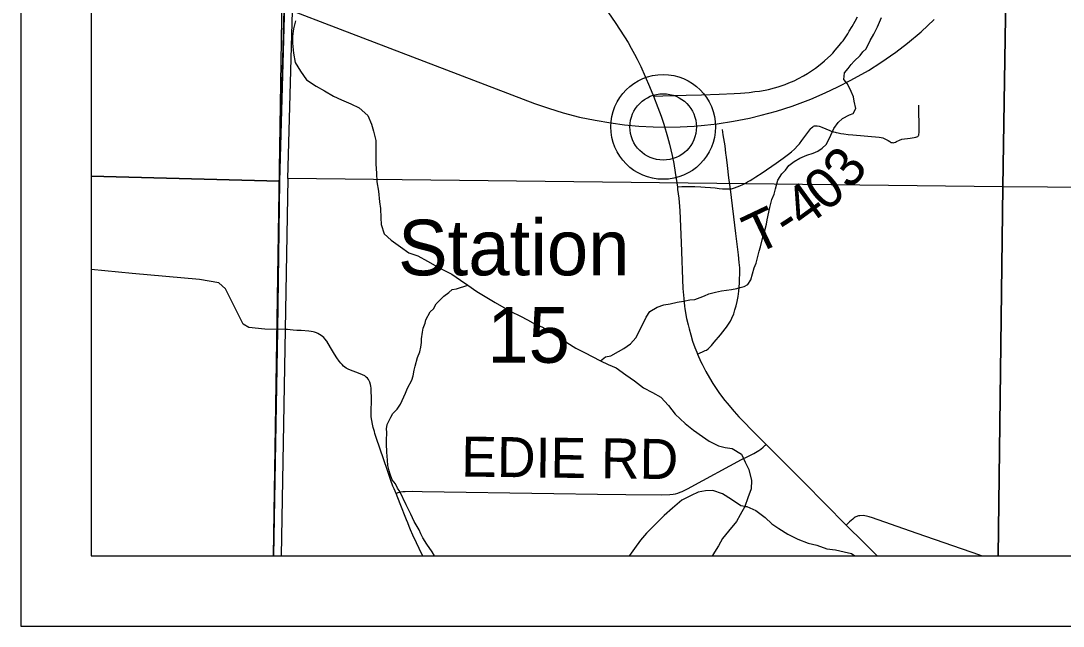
# Model space of a CAD drawing. Extents: x -1.2 to 34, y -8.5 to 22.
# Drawn here: x 2 to 3.48, y 14 to 14.86 of the extents above; entities that cross this region are included whole.
import ezdxf

# ---------------------------------------------------------------- set-up
doc = ezdxf.new("R2010")
doc.units = 0
for name, color, linetype in [('DV_X_County_Line', 7, 'Continuous'), ('GM_X_County_Road', 7, 'Continuous'), ('GM_X_Major_River', 7, 'Continuous'), ('GM_X_Minor_River', 7, 'Continuous'), ('GM_X_Rail_Line', 7, 'Continuous'), ('GM_X_Section', 7, 'Continuous'), ('GM_X_State_Route', 7, 'Continuous'), ('GM_X_Township_Road', 7, 'Continuous'), ('GM_X_Township_Road_Text', 7, 'Continuous'), ('GM_X_Unincorporated', 7, 'Continuous'), ('GM_X_Unincorporated_Location', 7, 'Continuous'), ('GM_X_Unincorporated_Text', 7, 'Continuous'), ('GM_X_US_Route', 7, 'Continuous'), ('SH_Cut_Line', 7, 'Continuous'), ('SH_Data', 7, 'Continuous')]:
    doc.layers.add(name, color=color, linetype=linetype)

msp = doc.modelspace()

# ---------------------------------------------------------------- linework, layer by layer
at = {"layer": 'DV_X_County_Line'}
msp.add_line((2.3586, 14.1), (2.465, 20.9), dxfattribs=at)
at = {"layer": 'GM_X_County_Road'}
for points in [[(3.0079, 14.6207), (3.0057, 14.637), (3.0035, 14.6544), (3.0021, 14.6661), (3.0014, 14.672), (3.0008, 14.6772), (3.0001, 14.6823), (2.9976, 14.6977), (2.9963, 14.7055)], [(3.0079, 14.6207), (3.0045, 14.6205), (2.9967, 14.6207), (2.9916, 14.6213), (2.986, 14.6219), (2.9793, 14.6227), (2.972, 14.6232), (2.9657, 14.6234), (2.9571, 14.6238), (2.9487, 14.6239), (2.9387, 14.6238), (2.9324, 14.6235)], [(2.9849, 14.4035), (2.9936, 14.4136), (3.0004, 14.4221), (3.0023, 14.4246), (3.0051, 14.4288), (3.0077, 14.4333), (3.0098, 14.4374), (3.0124, 14.4437), (3.0142, 14.4493), (3.0158, 14.4549), (3.0172, 14.4611), (3.0186, 14.4682), (3.0198, 14.4758), (3.0202, 14.4811), (3.0206, 14.4881), (3.021, 14.5052), (3.0209, 14.509), (3.0204, 14.5166), (3.0193, 14.5272), (3.0156, 14.5576), (3.0079, 14.6207)], [(2.9612, 14.3863), (2.972, 14.3913), (2.9736, 14.3922), (2.9761, 14.3938), (2.9777, 14.3952), (2.9809, 14.3988), (2.9849, 14.4035)], [(3.2061, 14.1548), (3.205, 14.1552), (3.203, 14.1559), (3.2012, 14.1563), (3.1988, 14.1568), (3.1961, 14.157), (3.1914, 14.1569), (3.1897, 14.1566), (3.1884, 14.1562), (3.1871, 14.1558), (3.1858, 14.1552), (3.1847, 14.1546), (3.1836, 14.1537), (3.1814, 14.1517), (3.1792, 14.1499), (3.1771, 14.1481), (3.1723, 14.1435)], [(3.3641, 14.1), (3.3619, 14.1008), (3.2731, 14.1315), (3.2633, 14.1348), (3.2082, 14.1541), (3.2061, 14.1548)]]:
    msp.add_lwpolyline(points, dxfattribs=at)
at = {"layer": 'GM_X_Major_River'}
msp.add_lwpolyline([(2.39, 14.8598), (2.3871, 14.8484), (2.3857, 14.8382), (2.3858, 14.8279), (2.3874, 14.8139), (2.3898, 14.8007), (2.3971, 14.7882), (2.4055, 14.7761), (2.4192, 14.7671), (2.4313, 14.7604), (2.4439, 14.7526), (2.4556, 14.7477), (2.4685, 14.7418), (2.4807, 14.7362), (2.4929, 14.7253), (2.4979, 14.7128), (2.501, 14.7029), (2.5042, 14.6897), (2.5043, 14.6662), (2.504, 14.6563), (2.5049, 14.6434), (2.5058, 14.6309), (2.5078, 14.6177), (2.5094, 14.6029), (2.511, 14.593), (2.5111, 14.5798), (2.5119, 14.5703), (2.5158, 14.5574), (2.5261, 14.5484), (2.5391, 14.5387), (2.5512, 14.5304), (2.5637, 14.526), (2.5774, 14.5185), (2.5919, 14.5103), (2.6017, 14.505), (2.612, 14.4998), (2.6245, 14.4916), (2.6348, 14.4844), (2.6477, 14.4754), (2.6736, 14.4597), (2.6861, 14.4526), (2.696, 14.447), (2.7097, 14.4403), (2.7196, 14.435), (2.7306, 14.4287), (2.7408, 14.4246), (2.753, 14.4175), (2.7659, 14.4092), (2.7754, 14.4029), (2.788, 14.3946), (2.8013, 14.3883), (2.8115, 14.3831), (2.8233, 14.3767), (2.8343, 14.3715), (2.8457, 14.3667), (2.8594, 14.3569), (2.8716, 14.3483), (2.8845, 14.3385), (2.897, 14.3318), (2.9088, 14.3254), (2.9199, 14.3134), (2.9294, 14.301), (2.9435, 14.2878), (2.9553, 14.2784), (2.9683, 14.2694), (2.9778, 14.2627), (2.9907, 14.2563), (3.0002, 14.2537), (3.01, 14.2523), (3.0237, 14.2444), (3.0287, 14.2327), (3.0337, 14.2225), (3.0376, 14.207), (3.037, 14.1949), (3.0325, 14.1823), (3.0281, 14.1701), (3.0218, 14.1583), (3.0165, 14.1484), (3.0049, 14.1351), (2.9967, 14.1244), (2.9907, 14.1141), (2.9829, 14.1011), (2.9822, 14.1)], dxfattribs=at)
at = {"layer": 'GM_X_Minor_River'}
for points in [[(2.8233, 14.3767), (2.8304, 14.3824), (2.838, 14.384), (2.8488, 14.3899), (2.8564, 14.3942), (2.8657, 14.4008), (2.8732, 14.4097), (2.8827, 14.4281), (2.8879, 14.4388), (2.8931, 14.4469), (2.9036, 14.4531), (2.9134, 14.4563), (2.9224, 14.458), (2.9319, 14.46), (2.9413, 14.4617), (2.95, 14.4634), (2.9572, 14.4642), (2.9647, 14.4666), (2.9711, 14.4694), (2.9771, 14.4718), (2.9866, 14.4746), (2.9952, 14.4762), (3.002, 14.4771), (3.0092, 14.478), (3.0168, 14.4796), (3.0217, 14.4808), (3.0273, 14.4824), (3.0326, 14.4852), (3.0367, 14.4921), (3.0417, 14.5089), (3.0443, 14.5158), (3.0486, 14.5326), (3.0507, 14.5387), (3.0547, 14.5563), (3.0565, 14.5621), (3.059, 14.5712), (3.06, 14.577), (3.0636, 14.5945), (3.0668, 14.606), (3.0697, 14.6136), (3.0719, 14.6213), (3.0751, 14.6335), (3.081, 14.6424), (3.0859, 14.6478), (3.0907, 14.6543), (3.0982, 14.6598), (3.1065, 14.6648), (3.1162, 14.6692), (3.1253, 14.672), (3.1321, 14.6747), (3.1381, 14.679), (3.1437, 14.6841), (3.1485, 14.6929), (3.1547, 14.7071), (3.1606, 14.7155), (3.167, 14.7209), (3.1771, 14.7264), (3.182, 14.7284), (3.1857, 14.7353), (3.1836, 14.7456), (3.1824, 14.752), (3.1793, 14.7592), (3.1738, 14.7702), (3.1688, 14.7765), (3.1698, 14.7861), (3.175, 14.7922), (3.1791, 14.7976), (3.1836, 14.8027), (3.1918, 14.8104), (3.1959, 14.8158), (3.2007, 14.82), (3.2062, 14.8319), (3.2114, 14.8408), (3.2166, 14.8511), (3.2224, 14.8645)], [(2.6005, 14.4686), (2.6076, 14.4741), (2.6128, 14.4783), (2.6185, 14.4792), (2.6348, 14.4844)], [(2.5876, 14.1), (2.5842, 14.1057), (2.5764, 14.1166), (2.571, 14.1253), (2.5683, 14.1313), (2.5656, 14.1366), (2.5586, 14.1487), (2.5539, 14.1589), (2.5472, 14.1725), (2.5383, 14.191), (2.5348, 14.1959), (2.532, 14.2019), (2.5274, 14.2076), (2.5246, 14.2159), (2.5231, 14.2208), (2.5214, 14.2284), (2.5206, 14.2356), (2.5196, 14.247), (2.5191, 14.2588), (2.5194, 14.2638), (2.5196, 14.2752), (2.5195, 14.2801), (2.5202, 14.2866), (2.5253, 14.297), (2.5283, 14.302), (2.5346, 14.3082), (2.5391, 14.3151), (2.5439, 14.3258), (2.5464, 14.3308), (2.549, 14.3381), (2.5552, 14.3492), (2.557, 14.3557), (2.5588, 14.3637), (2.5599, 14.3691), (2.5631, 14.3817), (2.5668, 14.3897), (2.5682, 14.3962), (2.5689, 14.4027), (2.5692, 14.408), (2.5702, 14.4176), (2.5712, 14.4233), (2.5741, 14.4302), (2.5752, 14.4351), (2.5811, 14.4466), (2.5859, 14.4509), (2.59, 14.4578), (2.6005, 14.4686)], [(3.0281, 14.1701), (3.0224, 14.1709), (3.0091, 14.1799), (2.9966, 14.1881), (2.9829, 14.1925), (2.9723, 14.1921), (2.9621, 14.1905), (2.9519, 14.1855), (2.9388, 14.1789), (2.9256, 14.1674), (2.9136, 14.1571), (2.9012, 14.1449), (2.8885, 14.1322), (2.8802, 14.1219), (2.8713, 14.1105), (2.8642, 14.1002), (2.8641, 14.1)], [(3.0281, 14.1701), (3.0311, 14.1698), (3.044, 14.1642), (3.057, 14.1541), (3.0665, 14.1454), (3.0764, 14.1387), (3.0893, 14.1304), (3.1034, 14.1237), (3.1182, 14.1178), (3.1303, 14.1148), (3.1447, 14.11), (3.1568, 14.1082), (3.1693, 14.1057), (3.1795, 14.1031), (3.1846, 14.1)]]:
    msp.add_lwpolyline(points, dxfattribs=at)
at = {"layer": 'GM_X_Rail_Line'}
msp.add_lwpolyline([(2.3745, 14.8781), (2.4533, 14.8478), (2.5882, 14.7964), (2.7294, 14.7425), (2.7492, 14.7358), (2.7701, 14.7293), (2.7936, 14.7231), (2.8157, 14.7186), (2.8381, 14.7148), (2.8573, 14.7121), (2.8778, 14.7104), (2.898, 14.7092), (2.9154, 14.7089), (2.9365, 14.7092), (2.9561, 14.7104), (2.9709, 14.7117), (2.9888, 14.7135), (3.012, 14.7172), (3.0347, 14.7217), (3.0515, 14.7256), (3.0731, 14.7317), (3.0954, 14.7387), (3.122, 14.7487), (3.1421, 14.7576), (3.1604, 14.766), (3.1787, 14.7755), (3.204, 14.7894), (3.2215, 14.8006), (3.2429, 14.8151), (3.2591, 14.8282), (3.2787, 14.8443), (3.2972, 14.8616)], dxfattribs=at)
at = {"layer": 'GM_X_Section'}
for points in [[(3.4107, 15.6483), (3.3946, 14.624), (2.3794, 14.636), (2.4074, 15.6568)], [(3.4107, 15.6483), (4.4223, 15.6306), (4.409, 14.6166), (3.3946, 14.624)], [(2.3696, 14.1), (3.388, 14.1), (3.3946, 14.624), (2.3794, 14.636)], [(3.388, 14.1), (4.3964, 14.1), (4.409, 14.6166), (3.3946, 14.624)]]:
    msp.add_lwpolyline(points, close=True, dxfattribs=at)
at = {"layer": 'GM_X_State_Route'}
msp.add_lwpolyline([(2.8986, 14.7529), (2.9116, 14.7533), (2.9451, 14.7543), (2.9668, 14.7549), (2.992, 14.7556), (3.013, 14.7565), (3.0221, 14.7571), (3.0342, 14.7581), (3.0426, 14.7592), (3.0492, 14.7601), (3.0572, 14.7615), (3.0616, 14.7624), (3.0704, 14.7646), (3.0757, 14.7662), (3.0853, 14.7694), (3.0908, 14.7715), (3.0982, 14.7748), (3.1042, 14.7779), (3.1114, 14.7819), (3.1174, 14.7852), (3.1245, 14.7898), (3.1284, 14.7926), (3.1374, 14.7997), (3.1415, 14.8031), (3.1503, 14.8112), (3.1531, 14.8141), (3.1565, 14.8179), (3.1622, 14.8247), (3.1661, 14.8294), (3.1677, 14.8316), (3.1744, 14.8415), (3.1766, 14.845), (3.1805, 14.8516), (3.1848, 14.8593), (3.188, 14.8653)], dxfattribs=at)
at = {"layer": 'GM_X_Township_Road'}
for points in [[(3.151, 14.7032), (3.154, 14.7023), (3.1563, 14.7017), (3.1579, 14.7012), (3.1609, 14.7006), (3.1644, 14.6999), (3.169, 14.6992), (3.1748, 14.6983), (3.1814, 14.6977), (3.2192, 14.6946), (3.2218, 14.6942), (3.2242, 14.6936), (3.2271, 14.6924), (3.2297, 14.691), (3.2319, 14.6896), (3.2341, 14.6882), (3.2358, 14.6872), (3.2373, 14.6868), (3.239, 14.6867), (3.2404, 14.6869), (3.242, 14.6876), (3.2437, 14.6884), (3.248, 14.6903), (3.2514, 14.6915), (3.2549, 14.6922), (3.2592, 14.6928), (3.2632, 14.6932), (3.2689, 14.694), (3.271, 14.6945), (3.2726, 14.6949), (3.2737, 14.6956), (3.2743, 14.6962), (3.2749, 14.697), (3.2751, 14.6976), (3.2755, 14.6989), (3.2757, 14.7006), (3.2759, 14.7036), (3.2752, 14.7401)], [(3.0079, 14.6207), (3.0135, 14.6227), (3.0174, 14.624), (3.0212, 14.6255), (3.0253, 14.6274), (3.0294, 14.6292), (3.0322, 14.6309), (3.0357, 14.633), (3.0396, 14.6354), (3.0437, 14.638), (3.0529, 14.6441), (3.0728, 14.6578), (3.0825, 14.6646), (3.0902, 14.6702), (3.0947, 14.6739), (3.0989, 14.6777), (3.1037, 14.6825), (3.1058, 14.6849), (3.1093, 14.6896), (3.1221, 14.7069), (3.1231, 14.708), (3.1246, 14.7093), (3.1257, 14.71), (3.1273, 14.7105), (3.1288, 14.7107), (3.1309, 14.7106), (3.1336, 14.7102), (3.1352, 14.7097), (3.1378, 14.7088), (3.149, 14.7038), (3.151, 14.7032)], [(2.3764, 14.4215), (2.3463, 14.4217), (2.3236, 14.4242), (2.3159, 14.4287), (2.3024, 14.4555), (2.2905, 14.479), (2.2813, 14.4876), (2.2536, 14.4924), (2.1583, 14.5011), (2.1, 14.5064)], [(2.5328, 14.1885), (2.5316, 14.1916), (2.5301, 14.195), (2.5285, 14.199), (2.5256, 14.2068), (2.5226, 14.2153), (2.5207, 14.221), (2.5047, 14.2681), (2.5039, 14.2707), (2.5029, 14.2736), (2.5021, 14.2763), (2.5012, 14.2791), (2.5003, 14.2821), (2.4992, 14.2869), (2.4983, 14.2922), (2.4977, 14.2975), (2.4974, 14.3019), (2.4978, 14.3236), (2.4977, 14.3347), (2.4974, 14.3378), (2.497, 14.3407), (2.4965, 14.3433), (2.4956, 14.3464), (2.4948, 14.3484), (2.4938, 14.3502), (2.4923, 14.352), (2.4906, 14.3536), (2.4884, 14.3553), (2.4852, 14.357), (2.4817, 14.3585), (2.4657, 14.3646), (2.4639, 14.3655), (2.462, 14.3666), (2.4603, 14.3678), (2.4582, 14.3694), (2.4563, 14.3714), (2.4543, 14.3736), (2.4519, 14.3766), (2.4488, 14.3812), (2.4455, 14.3864), (2.44, 14.3956), (2.4344, 14.4046), (2.4317, 14.4079), (2.4301, 14.4098), (2.4284, 14.4115), (2.4264, 14.413), (2.4243, 14.4144), (2.4219, 14.4156), (2.4198, 14.4166), (2.417, 14.4175), (2.4151, 14.418), (2.4123, 14.4185), (2.4088, 14.4188), (2.3981, 14.4197), (2.392, 14.4201), (2.3866, 14.4205), (2.3826, 14.4209), (2.3787, 14.4213), (2.3764, 14.4215)], [(2.8592, 14.1872), (2.9102, 14.1867), (2.9218, 14.1869), (2.9262, 14.1875), (2.9297, 14.1881), (2.9329, 14.189), (2.9364, 14.1902), (2.939, 14.1913), (2.9479, 14.1956), (2.952, 14.1978), (3.0236, 14.2365), (3.0324, 14.2411), (3.0408, 14.2454), (3.0457, 14.2479), (3.0482, 14.2494), (3.0508, 14.2514), (3.0541, 14.2543), (3.0573, 14.2571), (3.0585, 14.2582)], [(2.5328, 14.1885), (2.536, 14.1897), (2.5395, 14.1906), (2.5426, 14.1912), (2.5459, 14.1914), (2.5562, 14.1915), (2.5701, 14.1914), (2.7569, 14.1883), (2.8192, 14.1876), (2.8592, 14.1872)], [(2.5707, 14.1), (2.5687, 14.1043), (2.5658, 14.1103), (2.5618, 14.1184), (2.5567, 14.1291), (2.5532, 14.1368), (2.5514, 14.1414), (2.5494, 14.1465), (2.5477, 14.1509), (2.5386, 14.1737), (2.5328, 14.1885)]]:
    msp.add_lwpolyline(points, dxfattribs=at)
at = {"layer": 'GM_X_Unincorporated'}
for radius in [0.0744, 0.0472]:
    msp.add_circle((2.9123, 14.7091), radius, dxfattribs=at)
at = {"layer": 'GM_X_Unincorporated_Location'}
msp.add_line((2.9123, 14.7091), (2.9123, 14.7091), dxfattribs=at)
at = {"layer": 'GM_X_Unincorporated_Text'}
for p, q in [((2.1, 20.6871), (2.1, 14.6393)), ((2.3867, 15.3183), (2.3672, 14.6322)), ((2.3672, 14.6322), (2.3867, 15.3183)), ((2.1, 14.6393), (2.3672, 14.6322)), ((2.3672, 14.6322), (2.3643, 14.4203)), ((2.3643, 14.4203), (2.3586, 14.1)), ((2.3586, 14.1), (8.2551, 14.1))]:
    msp.add_line(p, q, dxfattribs=at)
msp.add_lwpolyline([(2.1, 14.6393), (2.1, 14.1), (2.3586, 14.1), (2.3643, 14.4203), (2.3672, 14.6322)], close=True, dxfattribs=at)
at = {"layer": 'GM_X_US_Route'}
for points in [[(2.7188, 15.0404), (2.7362, 15.015), (2.7785, 14.9532), (2.8448, 14.8562), (2.8625, 14.8288), (2.8668, 14.8212), (2.8717, 14.8123), (2.8753, 14.8052), (2.8806, 14.7947), (2.893, 14.7664), (2.8986, 14.7529)], [(2.8986, 14.7529), (2.9046, 14.7368), (2.9092, 14.7243), (2.9132, 14.7132), (2.9183, 14.6952), (2.9213, 14.6848), (2.9251, 14.6687), (2.9272, 14.6571), (2.9294, 14.6443), (2.9315, 14.6299), (2.9324, 14.6235), (2.9328, 14.6204), (2.9343, 14.6079), (2.9353, 14.5962), (2.9358, 14.5897), (2.9377, 14.545), (2.9403, 14.4794), (2.9406, 14.4747), (2.9414, 14.4656), (2.9426, 14.4547), (2.9431, 14.4509), (2.9456, 14.4372), (2.9476, 14.4278), (2.949, 14.4221), (2.9513, 14.4137), (2.9541, 14.405), (2.9573, 14.3959), (2.96, 14.3892), (2.9612, 14.3863), (2.9659, 14.3754), (2.9676, 14.372), (2.973, 14.3615), (2.9779, 14.3528), (2.9828, 14.3448), (2.9874, 14.3377), (2.9924, 14.3305), (2.9999, 14.3206), (3.0031, 14.3166), (3.0132, 14.3048), (3.0198, 14.2975), (3.0291, 14.2877), (3.036, 14.2807), (3.0585, 14.2582), (3.1123, 14.2041), (3.1723, 14.1435), (3.1978, 14.1183), (3.216, 14.1)]]:
    msp.add_lwpolyline(points, dxfattribs=at)
at = {"layer": 'SH_Cut_Line'}
msp.add_lwpolyline([(2.465, 20.9), (2.1, 20.9), (2.1, 14.1), (2.3586, 14.1), (2.3643, 14.4203), (2.3672, 14.6322), (2.3867, 15.3183), (2.402, 16.1209), (2.4189, 17.3824), (2.4258, 17.6899), (2.4414, 19.0677), (2.4628, 20.1657), (2.4644, 20.6742)], close=True, dxfattribs=at)
msp.add_lwpolyline([(4.6867, 17.6371), (4.4093, 17.6489), (4.1759, 17.654), (3.3984, 17.6707), (2.8968, 17.6806), (2.4258, 17.6899), (2.4189, 17.3824), (2.402, 16.1209), (2.3867, 15.3183), (2.3672, 14.6322), (2.3643, 14.4203), (2.3586, 14.1), (8.9, 14.1)], dxfattribs=at)
at = {"layer": 'SH_Data'}
for p, q in [((2, 21), (2, 14)), ((2, 21), (2, 14)), ((2.1, 20.9), (2.1, 14.1)), ((2.1, 20.9), (2.1, 14.1)), ((2.1, 14.1), (8.9, 14.1)), ((2.1, 14.1), (2.1, 14.1)), ((2.1, 14.1), (8.9, 14.1)), ((2.1, 14.1), (2.1, 14.1)), ((2, 14), (9, 14)), ((2, 14), (9, 14))]:
    msp.add_line(p, q, dxfattribs=at)

# ---------------------------------------------------------------- texts
at = {"layer": 'GM_X_Township_Road_Text'}
for s, height, rotation, p in [('3', 0.0568, 51.2709, (3.1785, 14.6182)), ('0', 0.0568, 39.7112, (3.1428, 14.5869)), ('4', 0.0568, 35.9728, (3.1113, 14.5639)), ('T', 0.0568, 25.3977, (3.0435, 14.5271)), ('-', 0.0568, 32.9851, (3.0891, 14.5493)), ('EDIE RD', 0.05682, 359.296, (2.6252, 14.2125))]:
    msp.add_text(s, height=height, rotation=rotation, dxfattribs=at).set_placement(p)
at = {"layer": 'GM_X_Unincorporated_Text'}
for s, p in [('Station', (2.5357, 14.4983)), ('15', (2.6623, 14.3741))]:
    msp.add_text(s, height=0.07898, rotation=0, dxfattribs=at).set_placement(p)

doc.saveas('drawing.dxf')
